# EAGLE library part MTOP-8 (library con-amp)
AMP connector
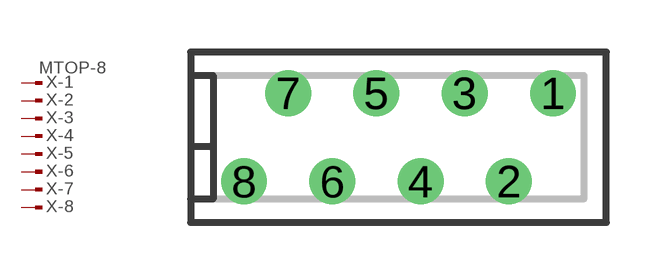
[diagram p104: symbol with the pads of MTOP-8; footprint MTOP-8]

Designator prefix X; gates -1=PIN-MV -2=PIN-M -3=PIN-M -4=PIN-M -5=PIN-M -6=PIN-M -7=PIN-M -8=PIN-M

## MTOP-8 (OC_FARNELL: unknown; OC_NEWARK: unknown)  [MTOP-8]
1  -1:1  pas
2  -2:1  pas
3  -3:1  pas
4  -4:1  pas
5  -5:1  pas
6  -6:1  pas
7  -7:1  pas
8  -8:1  pas

## Footprint MTOP-8 (pad centres in mm)
AMP connector
drill 0.813 round: 1 4.445,1.27; 2 3.175,-1.27; 3 1.905,1.27; 4 0.635,-1.27; 5 -0.635,1.27; 6 -1.905,-1.27; 7 -3.175,1.27; 8 -4.445,-1.27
